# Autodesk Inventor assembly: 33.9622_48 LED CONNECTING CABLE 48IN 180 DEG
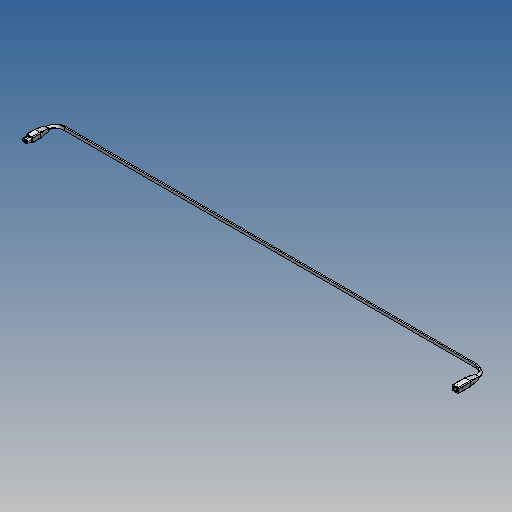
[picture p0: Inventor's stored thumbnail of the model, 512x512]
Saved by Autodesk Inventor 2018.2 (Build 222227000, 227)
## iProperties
Created: 2018-05
Part Number: 33.9622_48 LED CONNECTING CABLE 48IN 180 DEG
Document SubType Name: Assembly
Designer: amoles
Author: amoles
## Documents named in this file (4)
- Y:\INVENTOR LIBRARIES\PARTS LIBRARY\WORKSTATION\LIGHTS OUTWATER PLASTICS\33.9622_48 LED CONNECTING CABLE 48IN 180 DEG.iam
- Y:\INVENTOR LIBRARIES\PARTS LIBRARY\WORKSTATION\LIGHTS OUTWATER PLASTICS\SUBCOMPONENTS\33.9622 PLUG END MALE 90 DEG CORD.ipt
- Y:\INVENTOR LIBRARIES\PARTS LIBRARY\WORKSTATION\LIGHTS OUTWATER PLASTICS\SUBCOMPONENTS\33.9622 PLUG END FEMALE 90 DEG CORD.ipt
- Y:\INVENTOR LIBRARIES\PARTS LIBRARY\WORKSTATION\LIGHTS OUTWATER PLASTICS\SUBCOMPONENTS\33.9622_48 CORD for 180 DEG BEND.ipt
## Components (3 placed, 3 different names)
1. 33.9622 PLUG END MALE 90 DEG CORD:1 — Mate:1, Mate:2, Mate:3
2. 33.9622_48 CORD for 180 DEG BEND:1 — Mate:1, Mate:2, Mate:3, Mate:4, Mate:5, Mate:6
3. 33.9622 PLUG END FEMALE 90 DEG CORD:1 — Mate:4, Mate:5, Mate:6
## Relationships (6: Mate 6)
- Mate:1: 33.9622 PLUG END MALE 90 DEG CORD:1 ↔ 33.9622_48 CORD for 180 DEG BEND:1
- Mate:2: 33.9622 PLUG END MALE 90 DEG CORD:1 ↔ 33.9622_48 CORD for 180 DEG BEND:1
- Mate:3: 33.9622 PLUG END MALE 90 DEG CORD:1 ↔ 33.9622_48 CORD for 180 DEG BEND:1
- Mate:4: 33.9622_48 CORD for 180 DEG BEND:1 ↔ 33.9622 PLUG END FEMALE 90 DEG CORD:1
- Mate:5: 33.9622_48 CORD for 180 DEG BEND:1 ↔ 33.9622 PLUG END FEMALE 90 DEG CORD:1
- Mate:6: 33.9622_48 CORD for 180 DEG BEND:1 ↔ 33.9622 PLUG END FEMALE 90 DEG CORD:1
